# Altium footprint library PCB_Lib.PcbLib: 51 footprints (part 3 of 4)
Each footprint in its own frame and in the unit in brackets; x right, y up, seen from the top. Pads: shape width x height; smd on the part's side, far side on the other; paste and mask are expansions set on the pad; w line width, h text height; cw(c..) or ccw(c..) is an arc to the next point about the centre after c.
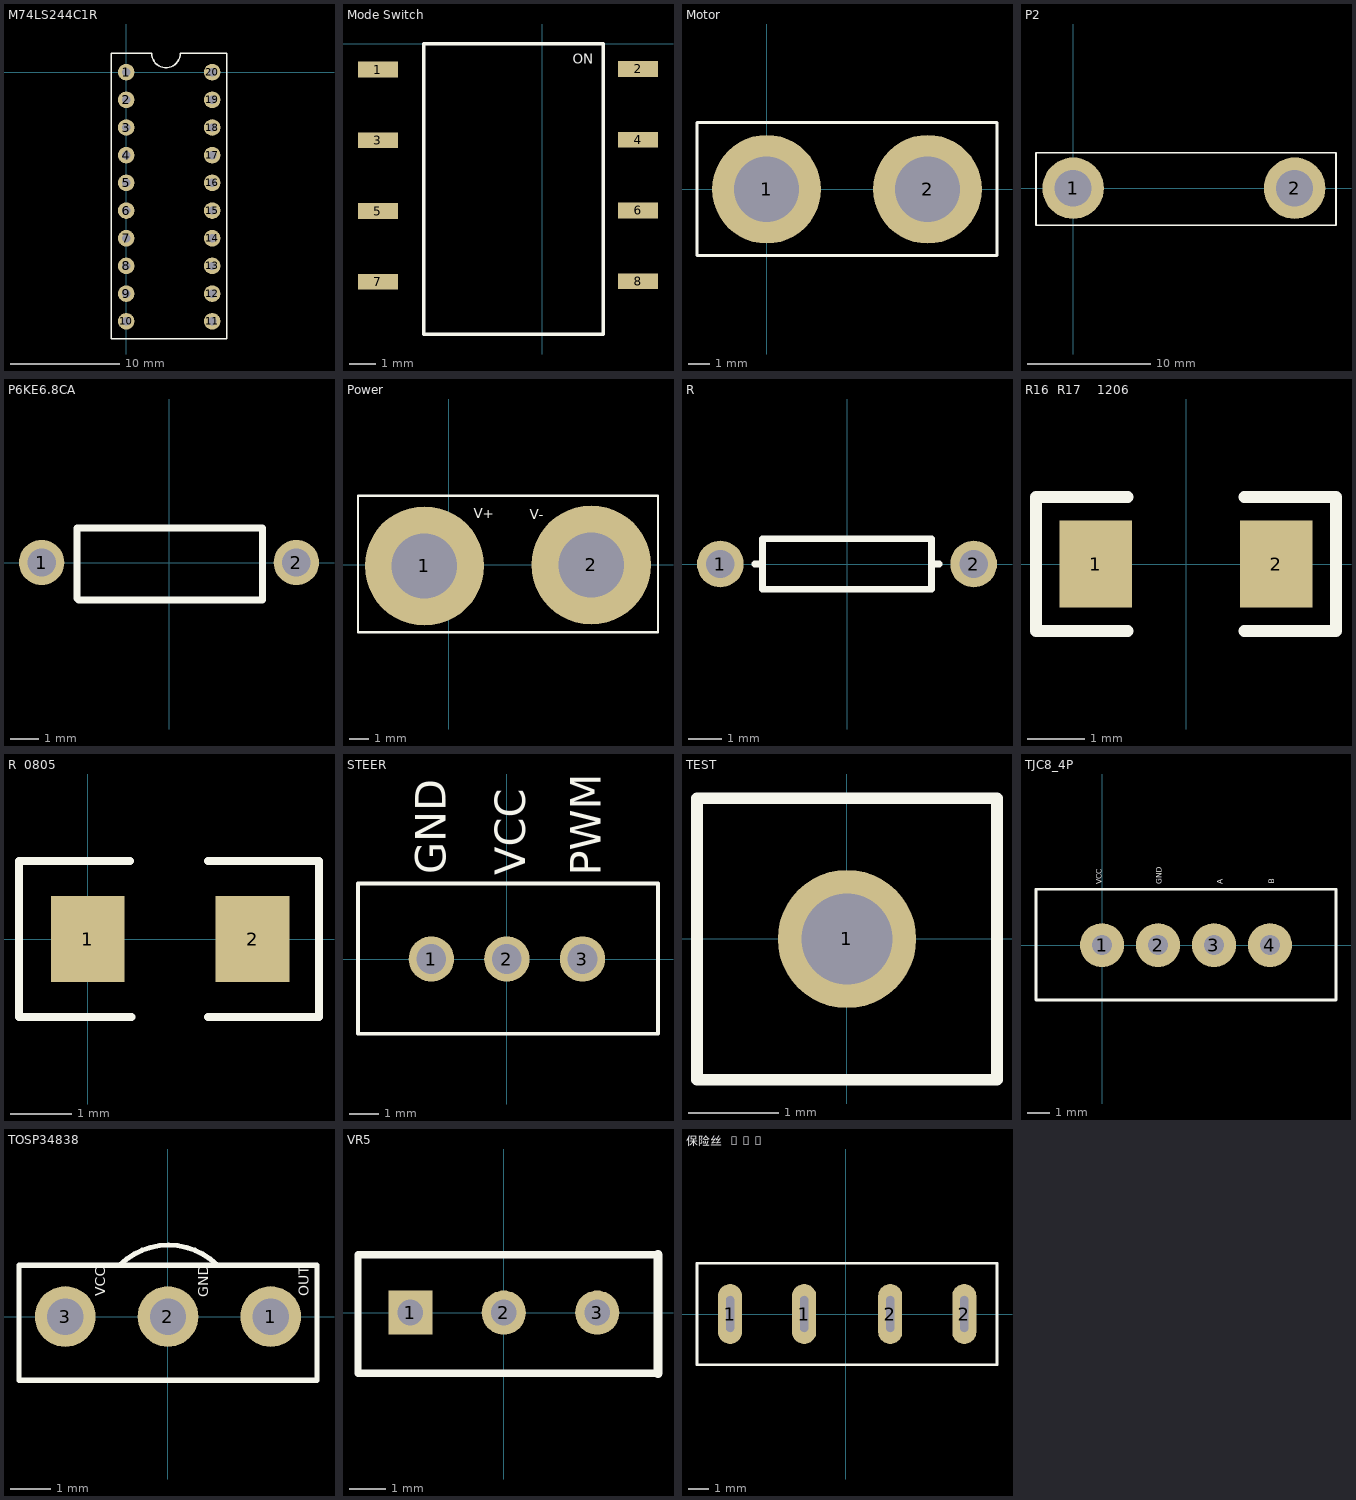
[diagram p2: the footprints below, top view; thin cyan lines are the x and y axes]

## M74LS244C1R [mil]
pads (20):
  round 60 hole 30: 1(0,0) 2(0,-100) 3(0,-200) 4(0,-300) 5(0,-400) 6(0,-500) 7(0,-600) 8(0,-700) 9(0,-800) 10(0,-900) 11(310.63,-900) 12(310.63,-800) 13(310.63,-700) 14(310.63,-600) 15(310.63,-500) 16(310.63,-400) 17(310.63,-300) 18(310.63,-200) 19(310.63,-100) 20(310.63,0)
Top Overlay:
  lines w5: -54.37,-964 363.63,-964 363.63,68 195.37,68 cw(c143.63,68) 91.89,68 -54.37,68 -54.37,-964

## Mode Switch [mil]
pads (8):
  rect 60x23.62 smd: 1(-246.83,-39) 2(144.17,-38) 3(-246.83,-145.33) 4(144.17,-144.33) 5(-246.83,-251.67) 6(144.17,-250.67) 7(-246.83,-358) 8(144.17,-357)
Top Overlay:
  lines w5: -178,-437 -178,0 92,0 92,-437 -178,-437
  text "ON" at 46,-30 h15

## Motor [mm]
pads (2):
  round 5 hole 3: 1(0,0) 2(7.4,0)
Top Overlay:
  lines w0.127: -3.2,-3.048 10.592,-3.048 10.592,3.073 -3.2,3.073 -3.2,-3.048

## P2 [mm]
pads (2):
  round 5 hole 3: 1(0,0) 2(18,0)
Top Overlay:
  lines w0.127: -3.023,-2.997 21.361,-2.997 21.361,2.87 -3.023,2.87 -3.023,-2.997

## P6KE6.8CA [mm]
pads (2):
  round 1.6 hole 1: 1(-4.5,0) 2(4.5,0)
Top Overlay:
  lines w0.254: -3.251,-1.27 -3.251,1.219 3.302,1.219 3.302,-1.321 -3.2,-1.321 -3.251,-1.27

## Power [mm]
pads (2):
  round 6.2 hole 3.4: 1(-1.27,-0.051) 2(7.4,0)
Top Overlay:
  lines w0.127: -4.724,-3.505 10.871,-3.505 10.871,3.607 -4.724,3.607 -4.724,-3.505
  text "V-" at 4.216,2.388 h0.51
  text "V+" at 1.295,2.438 h0.51

## R [mm] "Resistor; 2 Leads"
height 1.524
pads (2):
  round 1.4 hole 0.85: 1(-3.81,0) 2(3.81,0)
Top Overlay:
  lines w0.2: -2.769,0 -2.54,0 ; 2.769,0 2.54,0 ; 2.54,0 2.54,-0.762 -2.54,-0.762 -2.54,0.762 2.54,0.762 2.54,0

## R16  R17    1206 [mil]
height 501.97
pads (2):
  rect 50x60 smd: 1(-62,0) 2(62,0)
Top Overlay:
  lines w8: -40,-46 -103,-46 -103,46 -40,46 ; 40,-46 103,-46 103,46 40,46

## R  0805 [mm]
pads (2):
  rect 1.2x1.4 smd: 1(0,0) 2(2.68,0)
Top Overlay:
  lines w0.127: 0.686,1.27 -1.118,1.27 -1.118,-1.27 0.711,-1.27 ; 1.956,-1.27 3.734,-1.27 3.759,-1.27 3.759,1.27 1.956,1.27

## SOIC127P1030X265-20N [mil] "SOIC, 20-Leads, Body 10.5x7.5mm (max), Pitch 1.27mm, IPC Medium Density"
height 104.33

## STEER [mil]
pads (3):
  round 60 hole 39.37 square: 1(-100,0)
  round 60 hole 39.37: 2(0,0) 3(100,0)
Top Overlay:
  lines w5: -197,-99 -197,100 200,100 200,-99 -197,-99
  text "PWM" at 124,110 h40
  text "VCC" at 24,111 h40
  text "GND" at -81,112 h40

## TEST [mil]
pads (1):
  round 60 hole 39.37: 1(0,0)
Top Overlay:
  lines w5: -65,-61 -65,61 65,61 65,-61 -65,-61

## TJC8_4P [mm]
pads (4):
  round 2 hole 0.9 square: 1(0,0)
  round 2 hole 0.9: 2(2.54,0) 3(5.08,0) 4(7.62,0)
Top Overlay:
  lines w0.127: -3,-2.489 10.62,-2.489 10.62,2.54 -3,2.54 -3,-2.489
  text "B" at 7.823,2.794 h0.25
  text "A" at 5.486,2.769 h0.25
  text "GND" at 2.718,2.769 h0.25
  text "VCC" at -0.025,2.769 h0.25

## TOSP34838 [mm]
pads (3):
  round 1.5 hole 0.9: 1(2.54,0) 2(0,0) 3(-2.54,0)
Top Overlay:
  lines w0.127: -1.194,1.27 cw(c0.013,0.064) 1.219,1.27 ; -3.683,-1.575 -3.683,1.27 3.683,1.27 3.683,-1.575 -3.683,-1.575
  text "OUT" at 3.48,0.508 h0.25
  text "GND" at 0.991,0.483 h0.25
  text "VCC" at -1.549,0.508 h0.25

## VR5 [mm] "Potentiometer; 3 Leads"
pads (3):
  rect 1.2x1.2 hole 0.7: 1(-2.54,0)
  round 1.2 hole 0.7: 2(0,0) 3(2.54,0)
Top Overlay:
  lines w0.2: 4.191,-1.651 -3.962,-1.651 -3.962,1.575 4.191,1.575
  lines w0.254: 4.191,-1.651 4.191,1.575

## 保险丝  15A [mm]
pads (4):
  oval 1.2x3 hole 0.4 slot 1.8 at 90 deg: 1(-5.79,0) 1(-2.09,0) 2(2.21,0) 2(5.91,0)
Top Overlay:
  lines w0.127: -7.442,-2.54 -7.442,2.54 7.544,2.54 7.544,-2.54 -7.442,-2.54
